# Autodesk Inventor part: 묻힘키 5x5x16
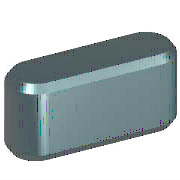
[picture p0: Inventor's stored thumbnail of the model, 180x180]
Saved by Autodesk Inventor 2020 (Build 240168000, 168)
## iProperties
Created: 2012-02
Part Number: 묻힘키 5x5x16
Material: 강철, 연강
Description: 평행 키
Document SubType Name: Modeling
Standard: JIS B 1301
Designer: mdu-01
Standards Organization: JIS
Language: ko-KR
Size Designation: 5x5x16
Categories: <MemberInstance><Categories><Category DisplayName="샤프트 부품" InternalName="7f7aeb1f-a693-4053-b835-cee3144e0d98" Mnemonic="SHFT"><Category DisplayName="키" Interna
Density: 1 g/cm^3
Appearance: 강철(1)
IsCustomPart: 1
Author: mdu-01
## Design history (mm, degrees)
sketch "스케치1"
  geometry: L1 (2.5, 2.5)-(13.5, 2.5); L2 (13.5, -2.5)-(2.5, -2.5); L3 (0, 9.4)-(0, -7.4) reference; L4 (-5, 0)-(30, 0) reference; L5 (16, 0)-(16, 7); A1 r 2.5 centre (2.5, 0) between (2.5, 2.5) and (2.5, -2.5); A2 r 2.5 centre (13.5, 0) between (13.5, -2.5) and (13.5, 2.5)
  constraints: 6 end point, 5 point on circle, 4 tangent, 3 point on line, 2 centre point, 1 horizontal, 1 parallel, 1 perpendicular
  dimensions: "d0" = 2.5 radius of A1 (= 0.5 x PB); "d13" = 2.5 radius of A2 (= 0.5 x PB); "d14" = 16 distance between parallel lines of L5 L3 (= NLG)
extrude "본체1" new body sketch "스케치1" taper "d3" = 0 deg; stored distance "d4" = 10
workplane "Work Plane3"
body "Solid1"
workplane "Work Plane1"
workplane "Work Plane2"
chamfer "모따기1" distance "d8" = 0.4 (= PHH); stored, may be unused: second distance "d9" = 0.4 (= PHH), angle "d15" = 45 deg
other parameters: "d1" = -3 (= -PNT), "d2" = 2 (= PH - PNT), "NLG" = 16 [user parameter; used in 3 equation terms], "PB" = 5 [user parameter; used in 2 equation terms], "PNT" = 3 [user parameter; used in 2 equation terms], "PH" = 5 [user parameter; used in 1 equation term], "PHH" = 0.4 [user parameter; used in 2 equation terms], "d10" = 0, "d16" = 0, "d17" = 0, "d18" = 0, "WDMIN" = 12 [user parameter], "PLB2" = 16 (= NLG) [user parameter], "WDMAX" = 17 [user parameter], "PLB1" = 16 (= NLG) [user parameter], "RR" = 0.16 [user parameter], "PUEB" = 2.3 [user parameter]
